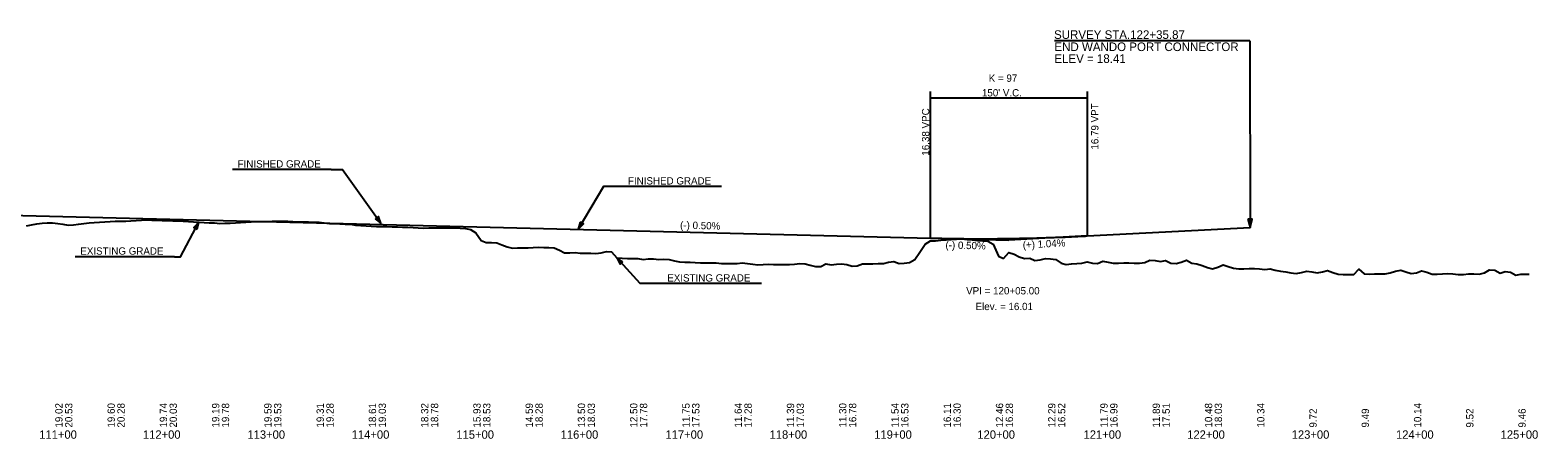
# Model space of a CAD drawing. Extents: x 2360994 to 2383826, y 330623 to 403123.
# Drawn here: x 2369894 to 2371337, y 336763 to 337154 of the extents above; entities that cross this region are included whole.
import ezdxf

# ---------------------------------------------------------------- set-up
doc = ezdxf.new("R2010")
doc.units = 0
for name, color, linetype in [('RD_DDB_GradeTX', 7, 'Continuous'), ('RD_DDB_Profile_EX', 7, 'Continuous'), ('RD_DDB_Profile_Lbl', 7, 'Continuous'), ('RD_DDB_Profile_PR', 7, 'Continuous'), ('RD_DDB_StaTX', 7, 'Continuous'), ('RD_DDB_StripGrade', 7, 'Continuous'), ('RD_DDB_VCLbl', 7, 'Continuous'), ('RD_TX_Profile', 7, 'Continuous')]:
    doc.layers.add(name, color=color, linetype=linetype)

msp = doc.modelspace()

# ---------------------------------------------------------------- linework, layer by layer
at = {"layer": 'RD_DDB_GradeTX'}
for p in [(2370755.6, 336954.8), (2370905.6, 336956.8)]:
    msp.add_line(p, (2370830.6, 336952.9), dxfattribs=at)
at = {"layer": 'RD_DDB_Profile_EX'}
for points in [[(2369890.6, 336966.5), (2369895.6, 336967.6), (2369900.6, 336968.5), (2369905.6, 336969.1), (2369910.6, 336969.2), (2369915.6, 336969.3), (2369920.6, 336968.8), (2369925.6, 336968), (2369930.6, 336967.2), (2369935.6, 336967.5), (2369940.6, 336968.2), (2369945.6, 336968.8), (2369950.6, 336969.3), (2369955.6, 336969.8), (2369960.6, 336970.1), (2369965.6, 336970.4), (2369970.6, 336970.6), (2369975.6, 336970.9), (2369980.6, 336971), (2369985.6, 336971.1), (2369990.6, 336971.3), (2369995.6, 336971.6), (2370000.6, 336971.9), (2370005.6, 336972.1), (2370010.6, 336972), (2370015.6, 336971.8), (2370020.6, 336971.7), (2370025.6, 336971.6), (2370030.6, 336971.3), (2370035.6, 336971.2), (2370040.6, 336970.8), (2370045.6, 336970.6), (2370050.6, 336970.4), (2370055.6, 336970.1), (2370060.6, 336969.8), (2370065.6, 336969.5), (2370070.6, 336969.2), (2370075.6, 336968.8), (2370080.6, 336968.9), (2370085.6, 336969.1), (2370090.6, 336969.5), (2370095.6, 336969.8), (2370100.6, 336970.1), (2370105.6, 336970.4), (2370110.6, 336970.6), (2370115.6, 336970.7), (2370120.6, 336970.7), (2370125.6, 336970.8), (2370130.6, 336971.1), (2370135.6, 336971), (2370140.6, 336970.8), (2370145.6, 336970.7), (2370150.6, 336970.4), (2370155.6, 336970.3), (2370160.6, 336970.3), (2370165.6, 336970.1), (2370170.6, 336970), (2370175.6, 336969.4), (2370180.6, 336968.8), (2370185.6, 336968.6), (2370190.6, 336968.3), (2370195.6, 336968.1), (2370200.6, 336968), (2370205.6, 336967.2), (2370210.6, 336966.7), (2370215.6, 336966.5), (2370220.6, 336966.2), (2370225.6, 336966), (2370230.6, 336965.8), (2370235.6, 336965.7), (2370240.6, 336965.6), (2370245.6, 336965.4), (2370250.6, 336965.3), (2370255.6, 336965.2), (2370260.6, 336965), (2370265.6, 336964.5), (2370270.6, 336964.3), (2370275.6, 336964.5), (2370280.6, 336964.6), (2370285.6, 336964.7), (2370290.6, 336964.6), (2370295.6, 336964.5), (2370300.6, 336964.5), (2370305.6, 336964.2), (2370310.6, 336963.9), (2370315.6, 336962.9), (2370320.6, 336959.7), (2370325.6, 336952.5)], [(2370325.6, 336952.5), (2370330.6, 336950.7), (2370335.6, 336950.4), (2370340.6, 336950.2), (2370345.6, 336948.3), (2370350.6, 336946.5), (2370355.6, 336945.1), (2370360.6, 336945.4), (2370365.6, 336945.4), (2370370.6, 336945.6), (2370375.6, 336945.8), (2370380.6, 336946.1), (2370385.6, 336945.7), (2370390.6, 336945.7), (2370395.6, 336945.6), (2370400.6, 336943.1), (2370405.6, 336940.7), (2370410.6, 336940.8), (2370415.6, 336940.9), (2370420.6, 336940.5), (2370425.6, 336940.4), (2370430.6, 336940.3), (2370435.6, 336939.9), (2370440.6, 336940.6), (2370445.6, 336941.8), (2370450.6, 336941.7), (2370455.6, 336935.9), (2370460.6, 336935.5), (2370465.6, 336935.4), (2370470.6, 336935.4), (2370475.6, 336935.4), (2370480.6, 336934.3), (2370485.6, 336934.8), (2370490.6, 336934.9), (2370495.6, 336934.4), (2370500.6, 336934.5), (2370505.6, 336934.2), (2370510.6, 336932.9), (2370515.6, 336932), (2370520.6, 336931.9), (2370525.6, 336931.7), (2370530.6, 336931.4), (2370535.6, 336931.2), (2370540.6, 336931), (2370545.6, 336931.1), (2370550.6, 336931), (2370555.6, 336930.5), (2370560.6, 336930.4), (2370565.6, 336930.4), (2370570.6, 336930.6), (2370575.6, 336931.1), (2370580.6, 336930.5), (2370585.6, 336929.8), (2370590.6, 336929.3), (2370595.6, 336929.5), (2370600.6, 336929.7), (2370605.6, 336929.5), (2370610.6, 336929.4), (2370615.6, 336929.4), (2370620.6, 336929.6), (2370625.6, 336929.9), (2370630.6, 336930.4), (2370635.6, 336930), (2370640.6, 336929), (2370645.6, 336927.6), (2370650.6, 336927.7), (2370655.6, 336930.3), (2370660.6, 336929.2), (2370665.6, 336929.8), (2370670.6, 336930.3), (2370675.6, 336929.4), (2370680.6, 336927.8), (2370685.6, 336928.2), (2370690.6, 336930.3), (2370695.6, 336930.2), (2370700.6, 336930.2), (2370705.6, 336930.4), (2370710.6, 336930.5), (2370715.6, 336931.8), (2370720.6, 336932.5), (2370725.6, 336930.6), (2370730.6, 336930.8), (2370735.6, 336931.4), (2370740.6, 336934.3), (2370745.6, 336941.3), (2370750.6, 336949.1), (2370755.6, 336952), (2370760.6, 336952.3), (2370765.6, 336952.7), (2370770.6, 336953.1), (2370775.6, 336953.4), (2370780.6, 336953.8), (2370785.6, 336954), (2370790.6, 336953.5), (2370795.6, 336953), (2370800.6, 336952.6), (2370805.6, 336952.1), (2370810.6, 336951.7), (2370815.6, 336948.9), (2370820.6, 336937.4), (2370825.6, 336935.2)], [(2370825.6, 336935.2), (2370830.6, 336941), (2370835.6, 336939.4), (2370840.6, 336936.7), (2370845.6, 336935.2), (2370850.6, 336935.6), (2370855.6, 336933.4), (2370860.6, 336933.9), (2370865.6, 336935.1), (2370870.6, 336935), (2370875.6, 336934.3), (2370880.6, 336930.8), (2370885.6, 336929.6), (2370890.6, 336930.3), (2370895.6, 336930.5), (2370900.6, 336930.9), (2370905.6, 336932.2), (2370910.6, 336930.9), (2370915.6, 336930.5), (2370920.6, 336932.7), (2370925.6, 336931.9), (2370930.6, 336930.8), (2370935.6, 336930.8), (2370940.6, 336931.1), (2370945.6, 336931.2), (2370950.6, 336930.8), (2370955.6, 336930.8), (2370960.6, 336931.3), (2370965.6, 336933.6), (2370970.6, 336933.3), (2370975.6, 336932.3), (2370980.6, 336933.4), (2370985.6, 336930.9), (2370990.6, 336930.5), (2370995.6, 336931.9), (2371000.6, 336933.6), (2371005.6, 336930.8), (2371010.6, 336930.2), (2371015.6, 336928.4), (2371020.6, 336926.6), (2371025.6, 336925.3), (2371030.6, 336927), (2371035.6, 336929.3), (2371040.6, 336927.7), (2371045.6, 336925.9), (2371050.6, 336925.4), (2371055.6, 336925.4), (2371060.6, 336925.7), (2371065.6, 336925.6), (2371070.6, 336925.3), (2371075.6, 336924.6), (2371080.6, 336925.3), (2371085.6, 336924), (2371090.6, 336923), (2371095.6, 336922.5), (2371100.6, 336921.6), (2371105.6, 336921), (2371110.6, 336922), (2371115.6, 336923), (2371120.6, 336922.4), (2371125.6, 336921.5), (2371130.6, 336922.6), (2371135.6, 336923.8), (2371140.6, 336922), (2371145.6, 336920.4), (2371150.6, 336920), (2371155.6, 336920.1), (2371160.6, 336920.1), (2371165.6, 336924.9), (2371170.6, 336920.7), (2371175.6, 336920.3), (2371180.6, 336920.6), (2371185.6, 336920.6), (2371190.6, 336920.7), (2371195.6, 336921.5), (2371200.6, 336923.2), (2371205.6, 336924), (2371210.6, 336922.5), (2371215.6, 336921), (2371220.6, 336921.7), (2371225.6, 336923.6), (2371230.6, 336922.3), (2371235.6, 336920.4), (2371240.6, 336920.4), (2371245.6, 336920.6), (2371250.6, 336920.8), (2371255.6, 336920.6), (2371260.6, 336919.8), (2371265.6, 336919.9), (2371270.6, 336920.5), (2371275.6, 336920.5), (2371280.6, 336920.4), (2371285.6, 336921.5), (2371290.6, 336924.4), (2371295.6, 336924), (2371300.6, 336921.1), (2371305.6, 336922.7), (2371310.6, 336922.3), (2371315.6, 336919.4), (2371320.6, 336920.3), (2371325.6, 336920.2)], [(2371325.6, 336920.2), (2371328.6, 336920.3)]]:
    msp.add_lwpolyline(points, dxfattribs=at)
at = {"layer": 'RD_DDB_Profile_PR'}
for p, q in [((2369525.6, 336985.5), (2370755.6, 336954.8)), ((2370905.6, 336956.8), (2371061.4, 336964.9))]:
    msp.add_line(p, q, dxfattribs=at)
msp.add_spline([(2370755.6, 336954.8), (2370758.6, 336954.7), (2370761.6, 336954.6), (2370764.6, 336954.6), (2370767.6, 336954.5), (2370770.6, 336954.5), (2370773.6, 336954.4), (2370776.6, 336954.4), (2370779.6, 336954.3), (2370782.6, 336954.3), (2370785.6, 336954.3), (2370788.6, 336954.2), (2370791.6, 336954.2), (2370794.6, 336954.2), (2370797.6, 336954.2), (2370800.6, 336954.2), (2370803.6, 336954.2), (2370806.6, 336954.2), (2370809.6, 336954.2), (2370812.6, 336954.2), (2370815.6, 336954.2), (2370818.6, 336954.2), (2370821.6, 336954.3), (2370824.6, 336954.3), (2370827.6, 336954.3), (2370830.6, 336954.4), (2370833.6, 336954.4), (2370836.6, 336954.4), (2370839.6, 336954.5), (2370842.6, 336954.6), (2370845.6, 336954.6), (2370848.6, 336954.7), (2370851.6, 336954.8), (2370854.6, 336954.8), (2370857.6, 336954.9), (2370860.6, 336955), (2370863.6, 336955.1), (2370866.6, 336955.2), (2370869.6, 336955.3), (2370872.6, 336955.4), (2370875.6, 336955.5), (2370878.6, 336955.6), (2370881.6, 336955.7), (2370884.6, 336955.8), (2370887.6, 336956), (2370890.6, 336956.1), (2370893.6, 336956.2), (2370896.6, 336956.4), (2370899.6, 336956.5), (2370902.6, 336956.7), (2370905.6, 336956.8)], degree=3, dxfattribs=at)
at = {"layer": 'RD_DDB_VCLbl'}
for p, q in [((2370755.6, 336954.8), (2370755.6, 337095.1)), ((2370905.6, 337095.1), (2370905.6, 336956.8)), ((2370755.6, 337088.9), (2370905.6, 337088.9))]:
    msp.add_line(p, q, dxfattribs=at)
at = {"layer": 'RD_TX_Profile'}
for p, q in [((2371061.1, 337143.5), (2370874.4, 337143.5)), ((2370182.2, 337020.2), (2370087.7, 337020.2)), ((2370555.8, 337004), (2370461.2, 337004)), ((2370032.4, 336936.9), (2369937.2, 336936.9)), ((2370593.9, 336911.2), (2370498.8, 336911.2))]:
    msp.add_line(p, q, dxfattribs=at)
for points in [[(2371061.1, 337143.5), (2371061.4, 336964.9)], [(2370182.2, 337020.2), (2370193.2, 337020.2), (2370229.8, 336968.9)], [(2370461.2, 337004), (2370442.9, 337004), (2370418.7, 336963.4)], [(2370032.4, 336936.9), (2370037.9, 336936.9), (2370055.6, 336970.1)], [(2370498.8, 336911.2), (2370478, 336911.2), (2370455.6, 336935.9)]]:
    msp.add_lwpolyline(points, dxfattribs=at)
for points in [[(2370054, 336963.3), (2370055.6, 336970.1), (2370050.8, 336965)], [(2370224.4, 336973.3), (2370229.8, 336968.9), (2370227.4, 336975.4)], [(2370420.6, 336970.1), (2370418.7, 336963.4), (2370423.7, 336968.3)], [(2371059.3, 336972.9), (2371061.4, 336964.9), (2371063.6, 336972.9)], [(2370461.4, 336932.1), (2370455.6, 336935.9), (2370458.8, 336929.7)]]:
    msp.add_lwpolyline(points, close=True, dxfattribs=at)

# ---------------------------------------------------------------- texts
at = {"layer": 'RD_DDB_GradeTX'}
for s, rotation, p in [('(-) 0.50%', 358.5679, (2370516, 336963.8)), ('(-) 0.50%', 358.5679, (2370769.9, 336944.8)), ('(+) 1.04%', 2.9767, (2370844.1, 336944.7))]:
    msp.add_text(s, height=7, rotation=rotation, dxfattribs=at).set_placement(p)
at = {"layer": 'RD_DDB_Profile_Lbl'}
for s, p in [('VPI = 120+05.00', (2370789.8, 336900.9)), ('Elev. = 16.01', (2370798.8, 336885.9))]:
    msp.add_text(s, height=7, dxfattribs=at).set_placement(p)
at = {"layer": 'RD_DDB_StaTX'}
for s, p in [('111+00', (2369902.9, 336762.9)), ('112+00', (2370002.1, 336762.9)), ('113+00', (2370102.1, 336762.9)), ('114+00', (2370201.9, 336762.9)), ('115+00', (2370302, 336762.9)), ('116+00', (2370401.8, 336762.9)), ('117+00', (2370502.1, 336762.9)), ('118+00', (2370601.7, 336762.9)), ('119+00', (2370701.8, 336762.9)), ('120+00', (2370800.5, 336762.9)), ('121+00', (2370902.1, 336762.9)), ('122+00', (2371001.3, 336762.9)), ('123+00', (2371101.3, 336762.9)), ('124+00', (2371201.1, 336762.9)), ('125+00', (2371301.2, 336762.9))]:
    msp.add_text(s, height=8, dxfattribs=at).set_placement(p)
at = {"layer": 'RD_DDB_StripGrade'}
for s, p in [('16.79 VPT', (2370916.4, 337039.4)), ('16.38 VPC', (2370754.5, 337033.6)), ('19.02', (2369925.2, 336773.6)), ('20.53', (2369934.6, 336773.6)), ('19.60', (2369975.2, 336773.6)), ('20.28', (2369984.6, 336773.6)), ('19.74', (2370025.2, 336773.6)), ('20.03', (2370034.6, 336773.6)), ('19.19', (2370075.2, 336773.6)), ('19.78', (2370084.6, 336773.6)), ('19.59', (2370125.2, 336773.6)), ('19.53', (2370134.6, 336773.6)), ('19.31', (2370175.2, 336773.6)), ('19.28', (2370184.6, 336773.6)), ('18.61', (2370225.2, 336773.6)), ('19.03', (2370234.6, 336773.6)), ('18.32', (2370275.2, 336773.6)), ('18.78', (2370284.6, 336773.6)), ('15.93', (2370325.2, 336773.6)), ('18.53', (2370334.6, 336773.6)), ('14.59', (2370375.2, 336773.6)), ('18.28', (2370384.6, 336773.6)), ('13.50', (2370425.2, 336773.6)), ('18.03', (2370434.6, 336773.6)), ('12.50', (2370475.2, 336773.6)), ('17.78', (2370484.6, 336773.6)), ('11.75', (2370525.2, 336773.6)), ('17.53', (2370534.6, 336773.6)), ('11.64', (2370575.2, 336773.6)), ('17.28', (2370584.6, 336773.6)), ('11.39', (2370625.2, 336773.6)), ('17.03', (2370634.6, 336773.6)), ('11.30', (2370675.2, 336773.6)), ('16.78', (2370684.6, 336773.6)), ('11.54', (2370725.2, 336773.6)), ('16.53', (2370734.6, 336773.6)), ('16.11', (2370775.2, 336773.6)), ('16.30', (2370784.6, 336773.6)), ('12.46', (2370825.2, 336773.6)), ('16.28', (2370834.6, 336773.6)), ('12.29', (2370875.2, 336773.6)), ('16.52', (2370884.6, 336773.6)), ('11.79', (2370925.2, 336773.6)), ('16.99', (2370934.6, 336773.6)), ('11.89', (2370975.2, 336773.6)), ('17.51', (2370984.6, 336773.6)), ('10.48', (2371025.2, 336773.6)), ('18.03', (2371034.6, 336773.6)), ('10.34', (2371075.2, 336773.6)), ('9.72', (2371125.2, 336773.6)), ('9.49', (2371175.2, 336773.6)), ('10.14', (2371225.2, 336773.6)), ('9.52', (2371275.2, 336773.6)), ('9.46', (2371325.2, 336773.6))]:
    msp.add_text(s, height=7, rotation=90, dxfattribs=at).set_placement(p)
at = {"layer": 'RD_DDB_VCLbl'}
for s, p in [('K = 97', (2370811.4, 337104.2)), ("150' V.C.", (2370804.9, 337090.2))]:
    msp.add_text(s, height=7, dxfattribs=at).set_placement(p)
at = {"layer": 'RD_TX_Profile'}
for s, height, p in [('SURVEY STA.122+35.87', 8.235, (2370873.9, 337145.2)), ('END WANDO PORT CONNECTOR', 8.235, (2370874.3, 337133.6)), ('ELEV = 18.41', 8.235, (2370874.2, 337122.3)), ('FINISHED GRADE', 7, (2370092.7, 337022.2)), ('FINISHED GRADE', 7, (2370466.2, 337006)), ('EXISTING GRADE', 7, (2369942.2, 336938.9)), ('EXISTING GRADE', 7, (2370503.8, 336913.2))]:
    msp.add_text(s, height=height, dxfattribs=at).set_placement(p)

doc.saveas('drawing.dxf')
